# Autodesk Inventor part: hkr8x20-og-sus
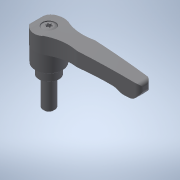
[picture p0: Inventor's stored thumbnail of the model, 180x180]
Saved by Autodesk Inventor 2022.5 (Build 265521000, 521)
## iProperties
Created: 2017-09
Part Number: hkr8x20-og-sus
Material: 一般
Document SubType Name: Modeling
Designer: imaocorp
Density: 1 g/cm^3
Appearance: 既定
Author: imaocorp
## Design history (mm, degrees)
node "hkr8x20-og-sus.x_t1"
node "hkr8x20-og-sus"
node "Base1"
